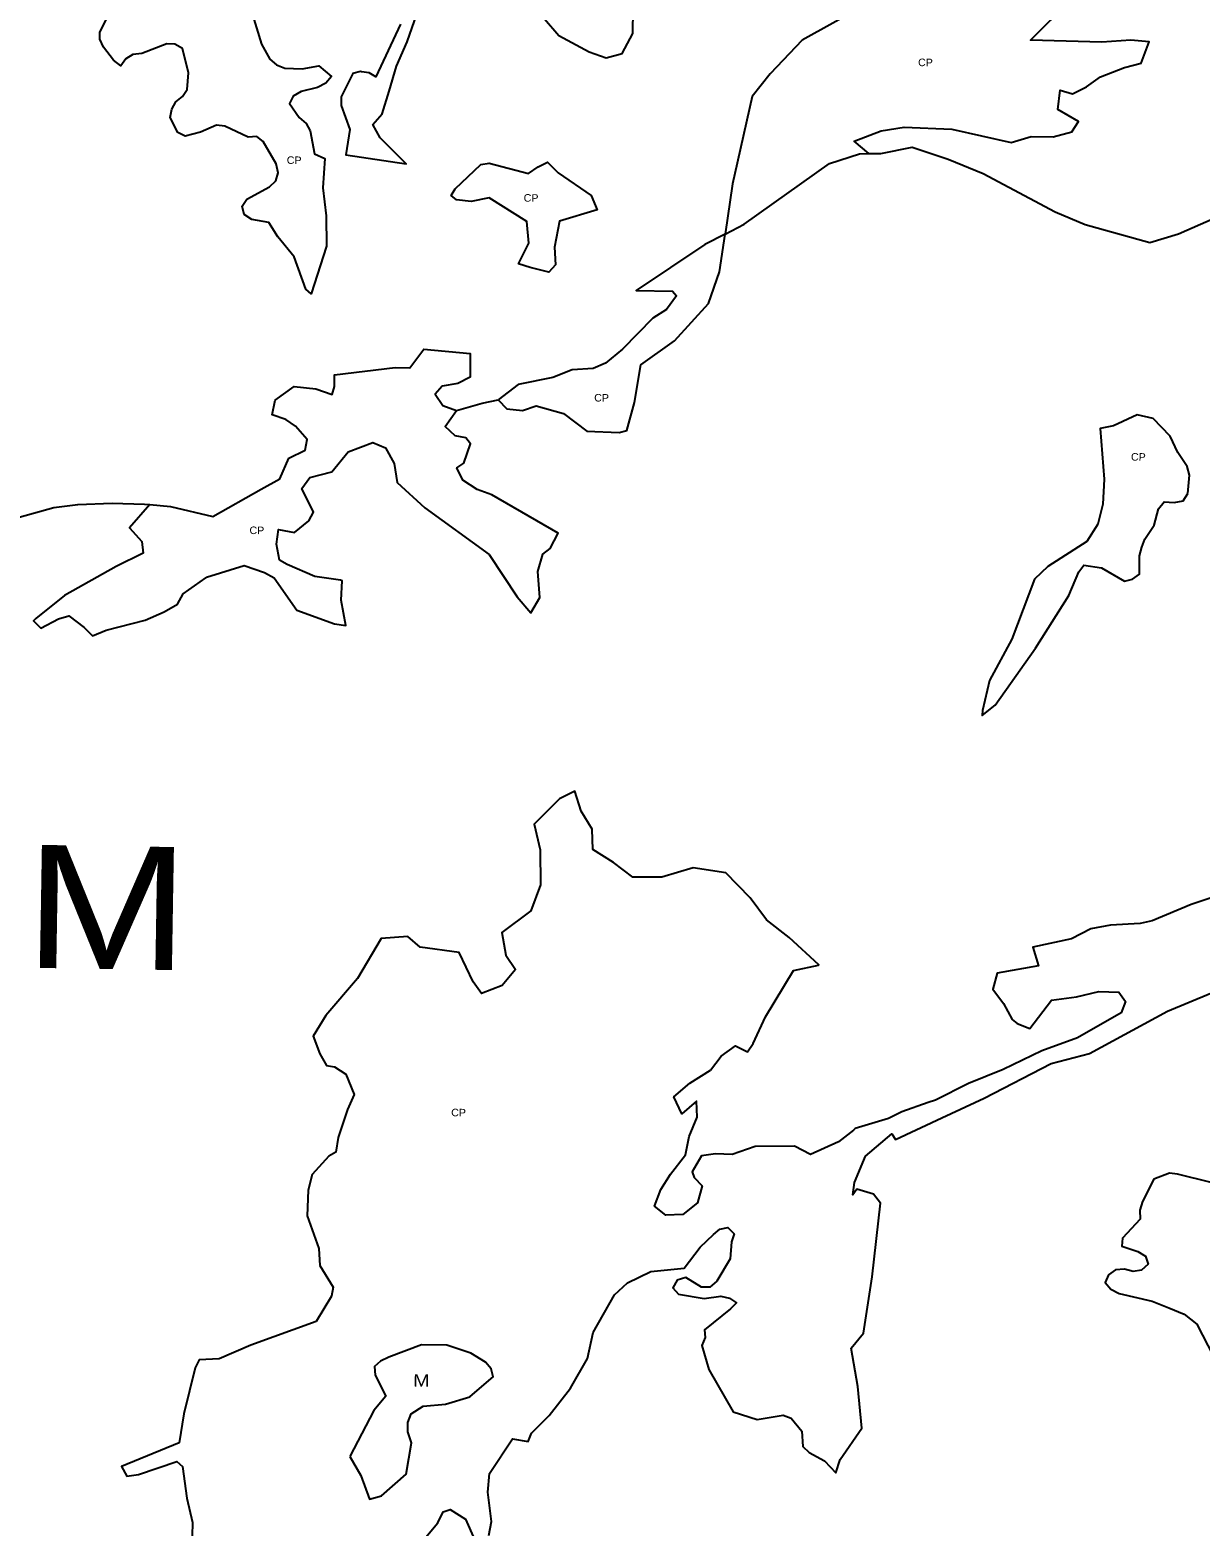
# Model space of a CAD drawing. Extents: x 713589 to 726391, y 7177764 to 7191819.
# Drawn here: x 718817 to 719806, y 7181207 to 7182472 of the extents above; entities that cross this region are included whole.
import ezdxf
from ezdxf.enums import TextEntityAlignment as Align

# ---------------------------------------------------------------- set-up
doc = ezdxf.new("R2010")
doc.units = 0
doc.header["$LTSCALE"] = 2.6
doc.layers.add('63', color=7, linetype='Continuous', lineweight=25)

msp = doc.modelspace()

# ---------------------------------------------------------------- linework, layer by layer
at = {"layer": '63'}
for points in [[(719130.09, 7182476.98), (719109.3, 7182432.48), (719103.69, 7182435.91), (719097.14, 7182436.81), (719096.45, 7182436.9), (719089.87, 7182435.26), (719079.99, 7182415.52), (719079.99, 7182408.28), (719087.23, 7182387.87), (719084, 7182366.64), (719135.07, 7182358.78), (719113.03, 7182380.83), (719106.87, 7182392.17), (719114.61, 7182401.3), (719120.54, 7182420.38), (719126.8, 7182441.44), (719135.68, 7182462.17), (719153.79, 7182513.83)], [(719004.32, 7182487.6), (719012.54, 7182459.95), (719019.78, 7182447.45), (719025.37, 7182442.51), (719032.28, 7182439.88), (719047.09, 7182439.22), (719061.24, 7182441.85), (719071.77, 7182432.63), (719067.16, 7182427.04), (719059.92, 7182423.42), (719046.1, 7182420.13), (719039.52, 7182416.18), (719036.23, 7182409.93), (719044.45, 7182398.08), (719050.37, 7182393.14), (719053.66, 7182386.89), (719057.43, 7182367.49), (719066.23, 7182363.51), (719064.64, 7182338.71), (719067.27, 7182315.02), (719067.6, 7182289.35), (719054.61, 7182248.92), (719050.02, 7182252.96), (719040.15, 7182280.28), (719026.33, 7182297.06), (719018.77, 7182309.24), (719004.62, 7182311.87), (718998.04, 7182316.15), (718996.39, 7182323.06), (719000.34, 7182328.98), (719019.43, 7182339.51), (719024.7, 7182344.45), (719026.67, 7182351.36), (719025.03, 7182358.93), (719014.17, 7182377.68), (719008.58, 7182381.96), (719001.34, 7182381.31), (718981.6, 7182390.85), (718974.69, 7182391.51), (718961.19, 7182385.59), (718948.03, 7182382.3), (718941.78, 7182385.27), (718935.53, 7182398.1), (718936.84, 7182405.01), (718940.14, 7182411.26), (718945.73, 7182415.87), (718949.68, 7182421.79), (718951, 7182435.94), (718945.74, 7182456.34), (718939.49, 7182459.97), (718932.58, 7182460.3), (718911.51, 7182452.07), (718903.95, 7182451.42), (718898.02, 7182447.8), (718893.74, 7182441.87), (718887.49, 7182446.48), (718878.94, 7182457.67), (718875.98, 7182464.25), (718875.98, 7182469.85), (718888.16, 7182494.86)], [(719251.85, 7182481.57), (719264.02, 7182467.42), (719289.69, 7182453.59), (719304.17, 7182448.65), (719317.66, 7182452.27), (719326.55, 7182469.05), (719326.88, 7182489.78)], [(719519.05, 7182490.73), (719469.78, 7182463.48), (719442.7, 7182435.13), (719427.56, 7182415.72), (719412.78, 7182350.86), (719410.76, 7182342.01), (719404.55, 7182299.52)], [(719526.23, 7182367.51), (719513.84, 7182377.93), (719536.53, 7182386.69), (719556.02, 7182389.92), (719596.38, 7182388.1), (719646.46, 7182376.88), (719663.5, 7182382.12), (719681.93, 7182381.78), (719697.72, 7182386.06), (719703.32, 7182394.61), (719685.88, 7182404.82), (719687.86, 7182421.27), (719698.39, 7182417.98), (719710.23, 7182423.9), (719722.08, 7182432.45), (719742.16, 7182440.35), (719756.31, 7182443.97), (719763.22, 7182462.06), (719747.76, 7182463.38), (719723.07, 7182461.74), (719662.86, 7182463.4), (719697.08, 7182497.94)], [(719526.23, 7182367.51), (719536.29, 7182367.77), (719562.62, 7182373.03), (719593.22, 7182362.82), (719622.84, 7182350.64), (719683.71, 7182318.38), (719709.05, 7182307.52), (719763.67, 7182292.37), (719788.02, 7182299.61), (719829.74, 7182318.04), (719830.47, 7182318.36), (719856.8, 7182332.5), (719891.69, 7182354.54), (719929.21, 7182382.51), (719956.52, 7182398.3), (719988.78, 7182420.34), (720024.98, 7182441.4), (720043.3, 7182449.85)], [(719404.55, 7182299.52), (719420.58, 7182307.77), (719492.99, 7182359.09), (719518.2, 7182367.31), (719526.23, 7182367.51)], [(719404.55, 7182299.52), (719387.34, 7182290.66), (719329.32, 7182251.85), (719360, 7182251.26), (719363.62, 7182247.31), (719355.06, 7182235.8), (719343.55, 7182228.56), (719317.87, 7182202.24), (719303.39, 7182190.39), (719293.19, 7182185.79), (719275.42, 7182184.8), (719258.97, 7182178.22), (719229.68, 7182172.31), (719212.75, 7182159.38)], [(719212.75, 7182159.38), (719219.93, 7182151.91), (719233.42, 7182150.26), (719244.94, 7182154.21), (719267.98, 7182147.95), (719287.72, 7182132.81), (719315.03, 7182131.82), (719321.61, 7182133.46), (719327.87, 7182157.15), (719333.34, 7182189.05), (719361.71, 7182209.4), (719390.58, 7182240.96), (719399.89, 7182267.64), (719404.55, 7182299.52)], [(718918.19, 7182070.83), (718935.85, 7182069.33), (718971.58, 7182060.81), (719012.5, 7182083.76), (719028.05, 7182092.48), (719035.84, 7182110.15), (719049.67, 7182116.73), (719051.31, 7182125.94), (719041.44, 7182137.13), (719033.22, 7182142.72), (719021.7, 7182146.68), (719024.33, 7182159.18), (719040.13, 7182170.69), (719058.56, 7182168.72), (719072.38, 7182163.78), (719074.36, 7182170.69), (719074.36, 7182180.56), (719125.69, 7182186.8), (719138.2, 7182186.47), (719149.78, 7182202.13), (719189.19, 7182198.51), (719189.2, 7182178.57), (719178.67, 7182173.3), (719165.51, 7182171), (719159.58, 7182164.09), (719165.83, 7182154.55), (719177.56, 7182150.49)], [(719177.56, 7182150.49), (719199.14, 7182156.45), (719212.75, 7182159.38)], [(718918.19, 7182070.83), (718901.13, 7182051.05), (718911.44, 7182039.75), (718912.47, 7182029.74), (718889.79, 7182018.62), (718846.01, 7181993.95), (718821.99, 7181974.54), (718820, 7181972.67), (718826, 7181966.38), (718841.14, 7181974.27), (718849.7, 7181976.91), (718862.86, 7181967.03), (718869.77, 7181959.79), (718881.29, 7181964.72), (718914.19, 7181973.27), (718930.32, 7181980.18), (718941.51, 7181986.76), (718946.45, 7181995.32), (718965.61, 7182009.04), (718966.19, 7182009.46), (718998.12, 7182019.33), (719015.23, 7182013.4), (719023.45, 7182008.79), (719042.53, 7181981.48), (719074.45, 7181969.96), (719083.99, 7181968.64), (719080.05, 7181990.03), (719080.95, 7182006.33), (719079.39, 7182006.81), (719057.68, 7182010.11), (719034.31, 7182020.31), (719027.88, 7182023.92), (719025.43, 7182037.42), (719026.97, 7182049.74), (719040.62, 7182047.23), (719052.75, 7182057.16), (719056.7, 7182064.4), (719046.83, 7182084.48), (719053.41, 7182093.69), (719072.17, 7182098.62), (719085.99, 7182115.4), (719106.73, 7182123.3), (719117.59, 7182118.69), (719124.82, 7182105.52), (719127.45, 7182089.4), (719150.81, 7182068.01), (719205.1, 7182028.51), (719228.79, 7181992.96), (719240.3, 7181979.47), (719247.88, 7181992.3), (719246.23, 7182014.35), (719250.51, 7182028.83), (719256.77, 7182033.76), (719263.35, 7182046.6), (719207.42, 7182079.18), (719194.91, 7182083.46), (719182.74, 7182091.36), (719177.8, 7182101.89), (719183.73, 7182105.84), (719189.32, 7182122.3), (719185.38, 7182127.23), (719176.49, 7182128.88), (719167.94, 7182136.78), (719177.56, 7182150.49)], [(718807.77, 7182060.29), (718837.11, 7182068.42), (718857.24, 7182070.96), (718886.28, 7182072.13), (718913.76, 7182071.21), (718918.19, 7182070.83)], [(719818.18, 7181739.18), (719798.53, 7181732.87), (719765.77, 7181718.82), (719755.53, 7181716.57), (719730.35, 7181715.3), (719713.9, 7181712.17), (719697.44, 7181703.84), (719664.79, 7181696.65), (719669.69, 7181680.93), (719634.48, 7181674.68), (719630.86, 7181661.19), (719640.07, 7181649.01), (719647.3, 7181635.52), (719651.58, 7181632.23), (719662.11, 7181627.95), (719680.54, 7181651.97), (719701.6, 7181654.6), (719720.69, 7181659.2), (719737.47, 7181658.54), (719743.07, 7181650.64), (719739.45, 7181641.1), (719702.59, 7181620.04), (719672.31, 7181609.19), (719639.73, 7181593.4), (719610.44, 7181581.56), (719582.47, 7181567.41), (719576.31, 7181565.26), (719554.16, 7181557.55), (719552.24, 7181556.61), (719542.65, 7181551.95), (719514.67, 7181543.4), (719513.02, 7181542.1), (719500.52, 7181532.22), (719476.83, 7181521.36), (719463.34, 7181528.6), (719430.1, 7181528.28), (719410.68, 7181521.37), (719396.53, 7181522.03), (719384.69, 7181520.39), (719376.79, 7181506.9), (719378.43, 7181501.96), (719385.34, 7181495.05), (719381.39, 7181480.57), (719368.88, 7181470.7), (719354.4, 7181470.05), (719344.86, 7181477.62), (719350.13, 7181491.77), (719358.36, 7181504.93), (719371.19, 7181521.05), (719374.16, 7181536.52), (719381.07, 7181552.97), (719380.5, 7181566.42), (719368.06, 7181555.8), (719361.33, 7181570.08), (719374.82, 7181581.6), (719392.27, 7181592.78), (719401.15, 7181604.63), (719413.33, 7181613.18), (719423.53, 7181608.25), (719428.47, 7181615.16), (719438.67, 7181637.86), (719462.47, 7181676.95), (719483.44, 7181681.42), (719483.8, 7181681.63), (719458.76, 7181704.79), (719439.68, 7181719.93), (719425.86, 7181738.36), (719405.13, 7181759.42), (719377.49, 7181763.71), (719351.16, 7181755.81), (719326.48, 7181755.82), (719310.36, 7181768.33), (719292.87, 7181779.15), (719292.27, 7181796.5), (719283.05, 7181811.64), (719277.57, 7181828.56), (719264.63, 7181822.17), (719243.24, 7181800.78), (719248.17, 7181779.06)], [(719248.17, 7181779.06), (719248.49, 7181749.45), (719240.26, 7181727.4), (719215.91, 7181708.98), (719219.19, 7181689.89), (719227.42, 7181677.71), (719216.23, 7181664.22), (719198.79, 7181657.65), (719191.55, 7181667.52), (719179.71, 7181692.2), (719146.8, 7181696.81), (719136.27, 7181705.7), (719113.89, 7181704.06), (719093.81, 7181670.17), (719067.15, 7181638.91), (719056.29, 7181621.47), (719061.88, 7181606.66), (719067.48, 7181596.79), (719074.39, 7181595.47), (719083.93, 7181589.22), (719091.12, 7181572.22), (719085.24, 7181559.6), (719077.34, 7181535.91), (719075.55, 7181523.4), (719069.66, 7181519.92), (719055.5, 7181504.46), (719052.21, 7181491.29), (719051.22, 7181469.57), (719061.09, 7181441.93), (719062.07, 7181427.45), (719073.26, 7181409.35), (719071.94, 7181401.78), (719058.82, 7181380.25), (719003.59, 7181360.2), (718976.94, 7181348.69), (718959.83, 7181347.7), (718956.53, 7181341.12), (718946.98, 7181302.29), (718943.03, 7181277.61), (718894.21, 7181257.68), (718898.82, 7181249.45), (718908.69, 7181250.77), (718940.94, 7181261.95), (718945.88, 7181257.67), (718949.49, 7181231.02), (718954.43, 7181210.28), (718954.1, 7181199.1)], [(719255.9, 7181300.77), (719273.97, 7181323.76), (719288.13, 7181349.09), (719293.07, 7181370.81), (719311.17, 7181402.73), (719322.03, 7181412.93), (719341.78, 7181422.47), (719370.08, 7181425.42), (719383.58, 7181443.19), (719394.77, 7181453.72), (719400.03, 7181458.32), (719406.94, 7181459.64), (719412.21, 7181454.37), (719409.9, 7181447.46), (719408.91, 7181433.31), (719397.72, 7181414.23), (719391.8, 7181409.29), (719384.56, 7181409.3), (719371.4, 7181417.53), (719364.16, 7181415.22), (719360.53, 7181408.64), (719365.14, 7181403.38), (719386.86, 7181399.75), (719401.01, 7181401.72), (719408.25, 7181400.08), (719414.26, 7181396.06), (719409.2, 7181390.93), (719409.09, 7181390.84), (719387.18, 7181373.2), (719387.84, 7181366.85), (719384.88, 7181359.94), (719390.8, 7181339.53), (719411.52, 7181303.99), (719431.59, 7181297.4), (719453.64, 7181301.02), (719460.55, 7181298.39), (719469.44, 7181287.53), (719470.42, 7181274.69), (719475.69, 7181269.43), (719488.52, 7181262.51), (719498.28, 7181252.45), (719501.79, 7181263.69), (719520.22, 7181290.02), (719516.94, 7181325.23), (719511.07, 7181357.59), (719521.62, 7181370.38), (719528.87, 7181418.09), (719536.12, 7181480.28), (719530.2, 7181487.85), (719516.05, 7181492.13), (719512.58, 7181487.22), (719514.01, 7181497.66), (719523.22, 7181520.04), (719545.6, 7181538.97), (719548.65, 7181534.14), (719587.97, 7181552.43), (719623.53, 7181568.99), (719680.14, 7181598.26), (719712.72, 7181606.81), (719778.54, 7181642.67), (719815.4, 7181657.8)], [(719815.66, 7181497.74), (719787.03, 7181504.66), (719780.45, 7181505.64), (719766.95, 7181500.71), (719757.41, 7181481.63), (719755.1, 7181474.39), (719755.43, 7181466.82), (719740.62, 7181450.7), (719739.96, 7181443.79), (719753.45, 7181439.51), (719760.03, 7181435.56), (719762.33, 7181428.64), (719756.74, 7181423.71), (719749.5, 7181422.39), (719742.26, 7181424.37), (719734.69, 7181424.04), (719728.77, 7181419.77), (719725.8, 7181413.19), (719730.74, 7181407.59), (719737.65, 7181403.97), (719765.62, 7181397.38), (719779.77, 7181391.69), (719792.6, 7181386.52), (719803.46, 7181377.96), (719817.6, 7181350.65)], [(719204.85, 7181199.38), (719207.15, 7181211.23), (719203.87, 7181235.91), (719205.51, 7181251.7), (719224.94, 7181280.99), (719238.1, 7181278.68), (719240.88, 7181285.79), (719255.9, 7181300.77)], [(719133.11, 7181175.7), (719161.74, 7181209.92), (719166.35, 7181219.46), (719172.27, 7181221.43), (719185.11, 7181213.21), (719192.67, 7181196.09)]]:
    msp.add_lwpolyline(points, dxfattribs=at)
for points in [[(719260.3, 7182288.46), (719261.29, 7182273.65), (719255.69, 7182267.4), (719239.78, 7182271.39), (719230.02, 7182274.32), (719238.58, 7182291.76), (719236.94, 7182310.19), (719205.15, 7182330.05), (719190.02, 7182327.17), (719177.51, 7182328.49), (719173, 7182332.01), (719176.4, 7182337.84), (719198.12, 7182358.24), (719205.03, 7182359.55), (719238.41, 7182350.65), (719246.62, 7182356.45), (719254.41, 7182360.25), (719263.6, 7182351.32), (719291.24, 7182332.22), (719296.5, 7182320.05), (719264.58, 7182310.51)], [(719795.79, 7182080.2), (719797.11, 7182095.67), (719795.14, 7182102.91), (719787.24, 7182114.75), (719780.99, 7182128.58), (719766.52, 7182143.71), (719753.03, 7182146.68), (719732.95, 7182137.47), (719721.62, 7182135.17), (719725.05, 7182092.26), (719724.05, 7182071.2), (719719.77, 7182054.41), (719710.56, 7182039.61), (719677.32, 7182018.55), (719666.13, 7182007.69), (719647.03, 7181957.02), (719628.27, 7181922.14), (719622.34, 7181896.81), (719621.92, 7181892.62), (719632.87, 7181901.21), (719667.1, 7181949.58), (719695.08, 7181994), (719703.64, 7182014.07), (719707.92, 7182019.67), (719722.73, 7182017.36), (719742.14, 7182006.17), (719749.05, 7182007.81), (719754.98, 7182012.09), (719754.98, 7182027.55), (719756.96, 7182034.79), (719759.59, 7182041.7), (719767.49, 7182053.55), (719771.11, 7182067.37), (719775.72, 7182073.29), (719784.28, 7182072.63), (719791.84, 7182073.95)], [(719087.34, 7181266.12), (719096.59, 7181250.08), (719103.83, 7181230), (719114.03, 7181232.96), (719135.09, 7181251.06), (719139.38, 7181277.71), (719136.42, 7181286.93), (719136.42, 7181294.82), (719139.05, 7181302.06), (719149.25, 7181308.64), (719168.34, 7181310.28), (719188.74, 7181316.53), (719196.97, 7181323.66), (719208.43, 7181333.57), (719206.85, 7181340.22), (719201.91, 7181345.82), (719189.74, 7181353.39), (719169.34, 7181360.3), (719147.95, 7181360.64), (719120.3, 7181350.11), (719113.39, 7181346.82), (719108.13, 7181342.21), (719108.78, 7181334.97), (719117.81, 7181317.02), (719107.62, 7181304.88)]]:
    msp.add_lwpolyline(points, close=True, dxfattribs=at)

# ---------------------------------------------------------------- texts
for s, height, width, p in [('CP', 6.4, 1.05, (719573.95, 7182441.43)), ('CP', 6.4, 1.05, (719040.22, 7182358.76)), ('CP', 6.4, 1.05, (719240.51, 7182326.87)), ('CP', 6.4, 1.05, (719300.14, 7182157.92)), ('CP', 6.4, 1.05, (719753.95, 7182107.96)), ('CP', 6.4, 1.05, (719008.69, 7182045.86)), ('M', 104, 1.2, (718881.1, 7181678.24)), ('CP', 6.4, 1.05, (719179.2, 7181553.67)), ('M', 10.4, 1.2, (719147.73, 7181325.21))]:
    msp.add_text(s, height=height, rotation=359.062, dxfattribs=dict(at, width=width)).set_placement(p, align=Align.CENTER)

doc.saveas('drawing.dxf')
